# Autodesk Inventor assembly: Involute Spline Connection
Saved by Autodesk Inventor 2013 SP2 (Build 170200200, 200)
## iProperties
Created: 2020-02
Part Number: Involute Spline Connection
Document SubType Name: Assembly
Designer: DELL
ClientObjectVersion: 1
Author: DELL
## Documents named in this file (1)
- C:\Users\DELL\Dropbox\Inventor\Projects\Quadcopter F450\Assemblies\Servo Accelerator Spline Makeup\Design Accelerator\Involute Spline Connection7.iam
